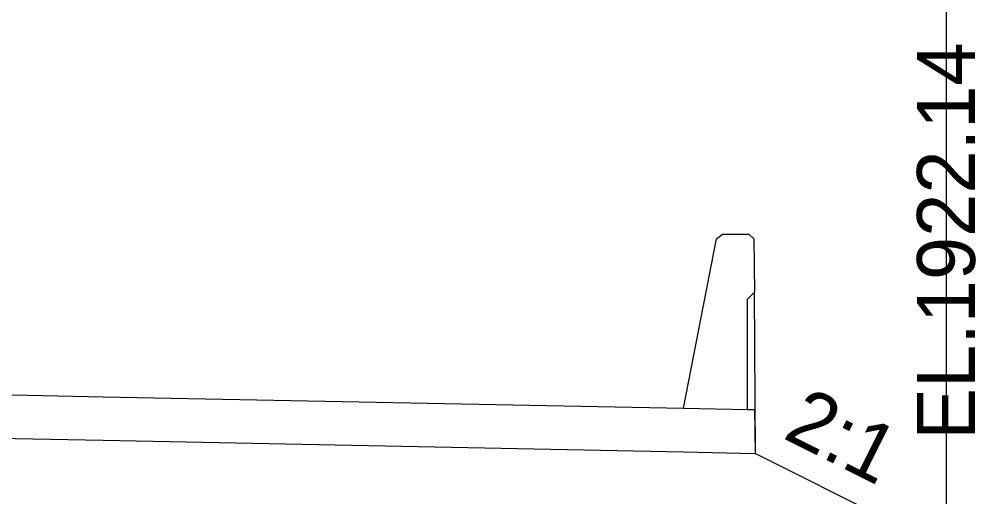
# Model space of a CAD drawing. Extents: x 1574 to 14903, y 7971 to 16537.
# Drawn here: x 13010.55 to 13027.03, y 8008.04 to 8016.26 of the extents above; entities that cross this region are included whole.
import ezdxf

# ---------------------------------------------------------------- set-up
doc = ezdxf.new("R2010")
doc.units = 0
for name, color, linetype in [('DESIGN - EARTHWORK - Excavation Limit Lines', 7, 'Continuous'), ('DESIGN - SURFACE - Bridge Surface Construction Lines', 7, 'Continuous'), ('DESIGN - TYPICAL - Finished Grade and Subgrade', 7, 'Continuous'), ('DESIGN - TYPICAL - Finished Grade Slopes Text', 7, 'Continuous'), ('DESIGN - TYPICAL - Slope Tie Text', 7, 'Continuous')]:
    doc.layers.add(name, color=color, linetype=linetype)

msp = doc.modelspace()

# ---------------------------------------------------------------- linework, layer by layer
at = {"layer": 'DESIGN - EARTHWORK - Excavation Limit Lines'}
msp.add_line((13026.519, 8033.389), (13026.519, 7980.889), dxfattribs=at)
at = {"layer": 'DESIGN - SURFACE - Bridge Surface Construction Lines'}
for p, q in [((13022, 8009.559), (13022.567, 8012.475)), ((13023.218, 8011.559), (13023.093, 8011.434)), ((13023.093, 8011.434), (13023.093, 8009.539)), ((13023.238, 8008.784), (13023.218, 8011.559))]:
    msp.add_line(p, q, dxfattribs=at)
at = {"layer": 'DESIGN - TYPICAL - Finished Grade and Subgrade'}
for p, q in [((13022.567, 8012.475), (13022.667, 8012.559)), ((13022.667, 8012.559), (13023.125, 8012.559)), ((13023.125, 8012.559), (13023.208, 8012.475)), ((13023.208, 8012.475), (13023.218, 8011.559)), ((13000, 8009.999), (13012, 8009.759)), ((13012, 8009.759), (13022, 8009.559)), ((13022, 8009.559), (13023.093, 8009.539)), ((13023.093, 8009.539), (13023.228, 8009.536)), ((13023.238, 8008.784), (13023.228, 8009.536)), ((13000, 8009.249), (13012, 8009.009)), ((13012, 8009.009), (13022, 8008.809)), ((13022, 8008.809), (13023.228, 8008.784)), ((13023.228, 8008.784), (13023.238, 8008.784)), ((13023.238, 8008.784), (13026.519, 8007.139))]:
    msp.add_line(p, q, dxfattribs=at)

# ---------------------------------------------------------------- texts
at = {"layer": 'DESIGN - TYPICAL - Finished Grade Slopes Text'}
msp.add_text('2:1', height=1, rotation=333.4349, dxfattribs=at).set_placement((13023.686, 8009.055))
at = {"layer": 'DESIGN - TYPICAL - Slope Tie Text'}
msp.add_text('EL.1922.14', height=1, rotation=90, dxfattribs=at).set_placement((13027.019, 8009.016))

doc.saveas('drawing.dxf')
